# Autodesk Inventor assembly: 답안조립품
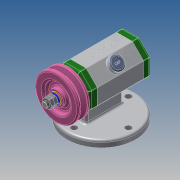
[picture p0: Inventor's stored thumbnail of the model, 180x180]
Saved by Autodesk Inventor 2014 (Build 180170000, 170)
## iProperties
Created: 2021-02
Part Number: 답안조립품
Document SubType Name: Assembly
Designer: kb542
Author: kb542
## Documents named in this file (14)
- C:\Users\kb542\Desktop\710204V1011\답안조립품.iam
- C:\Users\kb542\Desktop\710204V1011\본체.ipt
- C:\Users\kb542\Desktop\710204V1011\베어링 15 x 32 x 9.ipt
- C:\Users\kb542\Desktop\710204V1011\뒤커버.ipt
- C:\Users\kb542\Desktop\710204V1011\앞커버.ipt
- C:\Users\kb542\Desktop\710204V1011\오일 실 15 25 7.ipt
- C:\Users\kb542\Desktop\710204V1011\볼트 M4 x 12.ipt
- C:\Users\kb542\Desktop\710204V1011\축.ipt
- C:\Users\kb542\Desktop\710204V1011\키 3 x 3 x 12.ipt
- C:\Users\kb542\Desktop\710204V1011\V벨트풀리.ipt
- C:\Users\kb542\Desktop\710204V1011\와셔 8x17.ipt
- C:\Users\kb542\Desktop\710204V1011\스프링와셔 8.ipt
- C:\Users\kb542\Desktop\710204V1011\너트 M8.ipt
- C:\Users\kb542\Desktop\710204V1011\고무캡.ipt
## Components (2 placed, 2 different names)
1. V벨트풀리:1 — 각도:4
2. 고무캡:1 — 각도:3
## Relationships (2: Angle 2)
- 각도:3 [Angle]: 고무캡:1
- 각도:4 [Angle]: V벨트풀리:1
